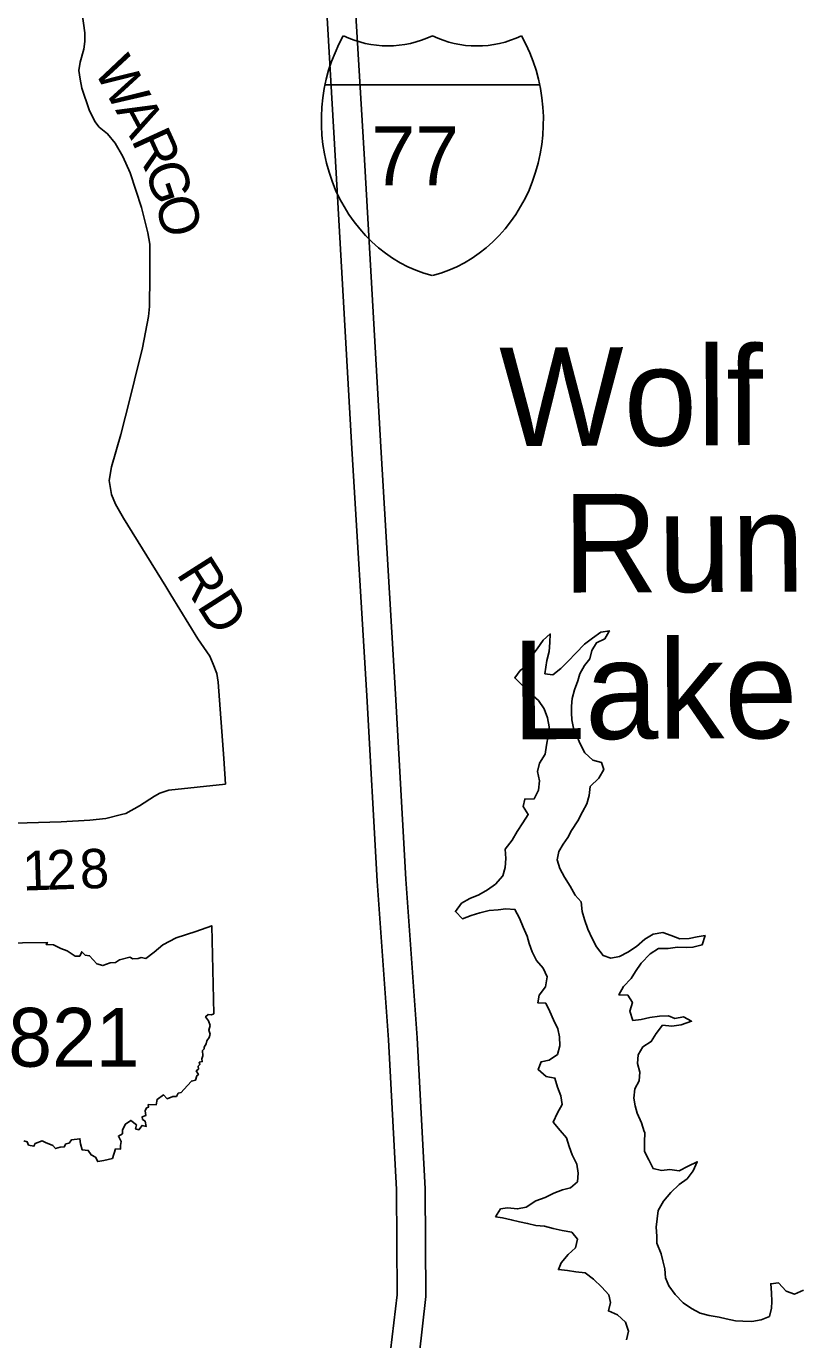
# Model space of a CAD drawing. Extents: x 0 to 34, y 0 to 22.
# Drawn here: x 25.646 to 26.755, y 11.27 to 13.16 of the extents above; entities that cross this region are included whole.
import ezdxf

# ---------------------------------------------------------------- set-up
doc = ezdxf.new("R2010")
doc.units = 0
for name, color, linetype in [('Default', 7, 'Continuous'), ('GM_X_County_Road_Text', 7, 'Continuous'), ('GM_X_Major_River', 7, 'Continuous'), ('GM_X_State_Route', 7, 'Continuous'), ('GM_X_Unincorporated_Text', 7, 'Continuous')]:
    doc.layers.add(name, color=color, linetype=linetype)

msp = doc.modelspace()

# ---------------------------------------------------------------- linework, layer by layer
at = {"layer": 'Default'}
for points in [[(25.8536, 12.342), (25.8464, 12.3538), (25.7854, 12.4525), (25.7741, 12.4726), (25.768, 12.4862), (25.765, 12.5066), (25.768, 12.5259), (25.7816, 12.5725), (25.7949, 12.6256), (25.8011, 12.6506), (25.8128, 12.6975), (25.8211, 12.7426), (25.8226, 12.7566), (25.8233, 12.8005), (25.8232, 12.8463), (25.8206, 12.863), (25.8111, 12.8993), (25.7948, 12.9493), (25.7842, 12.9727), (25.7732, 12.9917), (25.7626, 13.0053), (25.7505, 13.0147), (25.7441, 13.023), (25.7362, 13.0397), (25.7256, 13.0711), (25.7229, 13.084), (25.7214, 13.0964), (25.7229, 13.1082), (25.7282, 13.1271), (25.7297, 13.1381), (25.73, 13.1506), (25.7262, 13.1782)], [(25.932, 12.0696), (25.9297, 12.1067), (25.9213, 12.2161), (25.9194, 12.2286), (25.9145, 12.2422), (25.9096, 12.2539), (25.8925, 12.2785), (25.8536, 12.342)], [(25.6305, 12.0135), (25.6959, 12.0151), (25.7371, 12.0178), (25.7598, 12.0201), (25.7824, 12.0258), (25.7887, 12.0271), (25.8085, 12.0383), (25.83, 12.0524), (25.8376, 12.0565), (25.8508, 12.0607), (25.932, 12.0696)], [(25.5679, 11.8402), (25.6761, 11.8418), (25.6744, 11.8388), (25.6846, 11.8382), (25.6955, 11.833), (25.7046, 11.8297), (25.7158, 11.822), (25.7225, 11.822), (25.7254, 11.8284), (25.7305, 11.8235), (25.7366, 11.8226), (25.7472, 11.8109), (25.7559, 11.8084), (25.7664, 11.8124), (25.7741, 11.8131), (25.7798, 11.817), (25.7947, 11.8204), (25.7988, 11.8184), (25.8067, 11.8188), (25.8107, 11.8203), (25.8175, 11.8189), (25.8295, 11.8278), (25.842, 11.8383), (25.8611, 11.8482), (25.8896, 11.8575), (25.9122, 11.8659), (25.9155, 11.7392)], [(25.9155, 11.7392), (25.9121, 11.7374), (25.907, 11.7383), (25.9035, 11.7348), (25.9078, 11.7288), (25.9098, 11.7225), (25.908, 11.7157), (25.9098, 11.71), (25.9086, 11.7052), (25.9054, 11.7004), (25.9042, 11.6959), (25.9014, 11.6912), (25.9016, 11.6885), (25.899, 11.6864), (25.8995, 11.6785), (25.8982, 11.6741), (25.8986, 11.6703), (25.8943, 11.6693), (25.8953, 11.6662), (25.8926, 11.6637), (25.8932, 11.6596), (25.8901, 11.6569), (25.893, 11.6516), (25.8907, 11.65), (25.8887, 11.6435), (25.8831, 11.6422), (25.8722, 11.6304), (25.8683, 11.6259), (25.864, 11.6248), (25.8615, 11.6202), (25.8562, 11.6202), (25.848, 11.617), (25.8428, 11.6225), (25.8336, 11.6159), (25.8325, 11.6083), (25.8209, 11.6085), (25.8213, 11.6047), (25.8187, 11.6036), (25.8164, 11.5997), (25.8177, 11.5928), (25.8123, 11.5911), (25.8129, 11.5871), (25.8165, 11.5848), (25.818, 11.5771), (25.8122, 11.5786), (25.8075, 11.5722), (25.8026, 11.5738), (25.8042, 11.5792), (25.7959, 11.5857), (25.7881, 11.5805), (25.7841, 11.5721), (25.784, 11.5665), (25.7782, 11.5631), (25.7819, 11.5552), (25.7812, 11.5497), (25.7813, 11.5445), (25.7741, 11.5447), (25.7696, 11.5307)], [(25.7696, 11.5307), (25.7571, 11.528), (25.7484, 11.5264), (25.7452, 11.5328), (25.739, 11.5361), (25.7348, 11.5425), (25.7259, 11.5434), (25.7237, 11.5522), (25.7227, 11.5593), (25.7104, 11.5576), (25.7071, 11.5532), (25.7027, 11.552), (25.7002, 11.5476), (25.6942, 11.5473), (25.6878, 11.5452), (25.6836, 11.5495), (25.6732, 11.5538), (25.6685, 11.5561), (25.6586, 11.5526), (25.6565, 11.5485), (25.6488, 11.5503), (25.6469, 11.5549), (25.6422, 11.5563)]]:
    msp.add_lwpolyline(points, dxfattribs=at)
for centre, major_axis, start_param, end_param in [((26.2758, 13.0243), (0, -0.2289), 4.15077, 6.05619), ((26.1655, 13.3144), (0, -0.1826), 5.88324, 6.683049), ((26.1831, 13.0243), (0, -0.2289), 0.227007, 2.13242), ((26.2935, 13.3144), (0, -0.1827), 5.883359, 6.683012)]:
    msp.add_ellipse(centre, major_axis=major_axis, ratio=0.9, start_param=start_param, end_param=end_param, dxfattribs=at)
at = {"layer": 'GM_X_Major_River'}
msp.add_line((26.0756, 13.0758), (26.3838, 13.0758), dxfattribs=at)
for points in [[(26.4845, 12.29), (26.4717, 12.288), (26.4597, 12.2796), (26.448, 12.2711), (26.4357, 12.2581), (26.4248, 12.2466), (26.414, 12.2359), (26.4028, 12.2267), (26.3914, 12.2285), (26.3924, 12.2379), (26.3942, 12.2474), (26.3975, 12.2603), (26.3985, 12.2732), (26.3991, 12.2857), (26.389, 12.2765), (26.3801, 12.2643), (26.3726, 12.254), (26.3675, 12.2411), (26.3555, 12.233), (26.348, 12.2223), (26.3705, 12.2002), (26.382, 12.1898), (26.3904, 12.1777), (26.3951, 12.1649), (26.3975, 12.1521), (26.3961, 12.1392), (26.3936, 12.1256), (26.3915, 12.1127), (26.3833, 12.0997), (26.3808, 12.0876), (26.3836, 12.0743), (26.3822, 12.0611), (26.3759, 12.0485), (26.3623, 12.048), (26.3601, 12.0374), (26.3674, 12.0261), (26.3596, 12.0139), (26.3514, 12.0013), (26.3444, 11.9891), (26.3343, 11.9762), (26.3352, 11.9625), (26.3342, 11.9497), (26.3309, 11.9375), (26.3201, 11.9257), (26.3088, 11.9176), (26.2961, 11.9103), (26.2833, 11.9048), (26.2712, 11.8983), (26.2627, 11.8861), (26.2726, 11.876), (26.2854, 11.8806), (26.2978, 11.8846), (26.311, 11.8877), (26.3239, 11.8886), (26.3352, 11.8903), (26.3481, 11.8893), (26.3546, 11.8765), (26.36, 11.864), (26.3658, 11.8509), (26.3686, 11.8403), (26.3732, 11.8282), (26.379, 11.8158), (26.3886, 11.8049), (26.3944, 11.7921), (26.3923, 11.7777), (26.383, 11.7659), (26.3812, 11.7549), (26.3925, 11.7546), (26.3983, 11.7426), (26.4037, 11.7305), (26.4099, 11.7177), (26.4123, 11.706), (26.4128, 11.6932), (26.4092, 11.6807), (26.3975, 11.6726), (26.3858, 11.6702), (26.3814, 11.6588), (26.3929, 11.6487), (26.4057, 11.6466), (26.4096, 11.6337), (26.4143, 11.6209), (26.4163, 11.6085), (26.4096, 11.5966), (26.4034, 11.583), (26.4133, 11.5713), (26.4225, 11.5605), (26.426, 11.548), (26.4307, 11.536), (26.4372, 11.5228), (26.4389, 11.5096), (26.4382, 11.4974), (26.4281, 11.4886), (26.4168, 11.4859), (26.404, 11.4812), (26.3916, 11.475), (26.3781, 11.4699), (26.3642, 11.4611), (26.3521, 11.4583), (26.3374, 11.46), (26.3276, 11.4584), (26.3201, 11.447)], [(26.535, 11.5681), (26.5339, 11.57), (26.53, 11.5821), (26.5238, 11.596), (26.521, 11.6066), (26.519, 11.6179), (26.5208, 11.6312), (26.5267, 11.6426), (26.5277, 11.6551), (26.5245, 11.6675), (26.5255, 11.68), (26.5322, 11.6915), (26.5442, 11.6991), (26.5513, 11.7106), (26.5606, 11.7228), (26.5739, 11.7214), (26.5871, 11.7231), (26.6021, 11.7285), (26.5907, 11.7349), (26.5783, 11.7324), (26.5688, 11.7361), (26.556, 11.7356), (26.542, 11.7336), (26.5296, 11.7308), (26.5179, 11.7295), (26.5132, 11.7431), (26.5172, 11.7556), (26.5107, 11.7658), (26.4978, 11.7664), (26.5041, 11.7786), (26.5153, 11.79), (26.5217, 11.7999), (26.5295, 11.8121), (26.5426, 11.8255), (26.5546, 11.8329), (26.5686, 11.833), (26.5821, 11.835), (26.5942, 11.8344), (26.6041, 11.8349), (26.6176, 11.8385), (26.6216, 11.8517), (26.61, 11.8497), (26.5986, 11.8477), (26.5854, 11.8472), (26.5729, 11.852), (26.5608, 11.856), (26.5468, 11.8536), (26.5348, 11.8463), (26.5228, 11.8359), (26.5104, 11.8278), (26.4984, 11.8216), (26.4863, 11.8192), (26.4749, 11.8229), (26.4654, 11.8353), (26.4592, 11.8473), (26.453, 11.8609), (26.448, 11.8748), (26.4448, 11.8865), (26.4432, 11.9001), (26.4348, 11.9099), (26.4274, 11.9227), (26.4197, 11.9358), (26.4128, 11.9483), (26.4089, 11.9607), (26.4111, 11.9725), (26.4177, 11.9831), (26.4241, 11.993), (26.4296, 12.0029), (26.4386, 12.0167), (26.4452, 12.0296), (26.4515, 12.041), (26.4548, 12.0532), (26.4562, 12.0661), (26.4689, 12.0783), (26.476, 12.0905), (26.4728, 12.1007), (26.4603, 12.1039), (26.4489, 12.1148), (26.442, 12.1276), (26.4365, 12.14), (26.4326, 12.1502), (26.4299, 12.1623), (26.4294, 12.1721), (26.4297, 12.182), (26.4303, 12.1926), (26.434, 12.2055), (26.4387, 12.2184), (26.4413, 12.2283), (26.4483, 12.2405), (26.4558, 12.25), (26.4587, 12.2618), (26.4654, 12.2728), (26.4774, 12.2786), (26.4834, 12.2889), (26.4845, 12.29)], [(26.7633, 11.3417), (26.7502, 11.3355), (26.738, 11.3399), (26.7273, 11.3519), (26.716, 11.3506), (26.7169, 11.3378), (26.7178, 11.3253), (26.7171, 11.3158), (26.7142, 11.3037), (26.7022, 11.2986), (26.6886, 11.2966), (26.6757, 11.2968), (26.6655, 11.2975), (26.6519, 11.3003), (26.6417, 11.3025), (26.6277, 11.305), (26.6144, 11.3083), (26.6022, 11.3153), (26.5901, 11.3231), (26.5786, 11.3351), (26.5694, 11.3479), (26.5648, 11.3592), (26.5635, 11.372), (26.5607, 11.3837), (26.5587, 11.3939), (26.5521, 11.409), (26.552, 11.4192), (26.5515, 11.4321), (26.5525, 11.4442), (26.5543, 11.4563), (26.5617, 11.4693), (26.5722, 11.4819), (26.5842, 11.4933), (26.5958, 11.5018), (26.6047, 11.5132), (26.6103, 11.5262), (26.5975, 11.52), (26.5843, 11.513), (26.5711, 11.5152), (26.559, 11.5135), (26.5469, 11.5164), (26.5407, 11.5292), (26.5345, 11.5412), (26.5344, 11.5545), (26.535, 11.5681)], [(26.3201, 11.447), (26.3303, 11.4456), (26.3428, 11.4427), (26.355, 11.4398), (26.3663, 11.4376), (26.3784, 11.4347), (26.3909, 11.4334), (26.403, 11.4301), (26.4163, 11.4272), (26.4299, 11.4247), (26.438, 11.4149), (26.4351, 11.4024), (26.4246, 11.3929), (26.4149, 11.3806), (26.4108, 11.3711), (26.4237, 11.3698), (26.4358, 11.368), (26.4494, 11.3663), (26.4612, 11.3573), (26.4731, 11.3457), (26.483, 11.3348), (26.4858, 11.3235), (26.4825, 11.3117), (26.4958, 11.3062), (26.5072, 11.2954), (26.5115, 11.2826), (26.5086, 11.27)]]:
    msp.add_lwpolyline(points, dxfattribs=at)
at = {"layer": 'GM_X_State_Route'}
for points in [[(25.9949, 10.7718), (26.0125, 10.8135), (26.0546, 10.9225), (26.0657, 10.953), (26.1189, 11.089), (26.1236, 11.1043), (26.1459, 11.1665), (26.1572, 11.2029), (26.1694, 11.2542), (26.1787, 11.3347), (26.1777, 11.4861), (26.1663, 11.7018), (26.1499, 11.9302), (26.1352, 12.1964), (26.1137, 12.5526), (26.0897, 12.974), (26.0747, 13.2305)], [(26.0332, 10.7556), (26.051, 10.798), (26.0935, 10.9079), (26.1046, 10.9383), (26.1581, 11.0753), (26.163, 11.0912), (26.1854, 11.1533), (26.1973, 11.192), (26.2104, 11.2469), (26.2203, 11.3325), (26.2193, 11.4873), (26.2078, 11.7044), (26.1914, 11.9329), (26.1767, 12.1988), (26.1552, 12.555), (26.1312, 12.9764), (26.1162, 13.2323)]]:
    msp.add_lwpolyline(points, dxfattribs=at)

# ---------------------------------------------------------------- texts
at = {"layer": 'Default'}
for s, p in [('77', (26.1419, 12.9314)), ('821', (25.6197, 11.663))]:
    msp.add_text(s, height=0.08462, dxfattribs=at).set_placement(p)
at = {"layer": 'GM_X_County_Road_Text'}
for s, rotation, p in [('W', 298.1998, (25.742, 13.0975)), ('A', 298.0656, (25.7731, 13.0396)), ('R', 294.6307, (25.7961, 12.9964)), ('G', 288.458, (25.815, 12.9556)), ('O', 284.2103, (25.8304, 12.9093)), ('RD', 302.5098, (25.8605, 12.3723)), ('1', 1.9414, (25.6408, 11.9163)), ('2', 1.9462, (25.6758, 11.9175)), ('8', 2.8385, (25.7237, 11.9187))]:
    msp.add_text(s, height=0.0567, rotation=rotation, dxfattribs=at).set_placement(p)
at = {"layer": 'GM_X_Unincorporated_Text'}
for s, p in [('Wolf', (26.326, 12.5558)), ('Run', (26.4173, 12.3452)), ('Lake', (26.3438, 12.134))]:
    msp.add_text(s, height=0.14175, rotation=0.2496, dxfattribs=at).set_placement(p)

doc.saveas('drawing.dxf')
